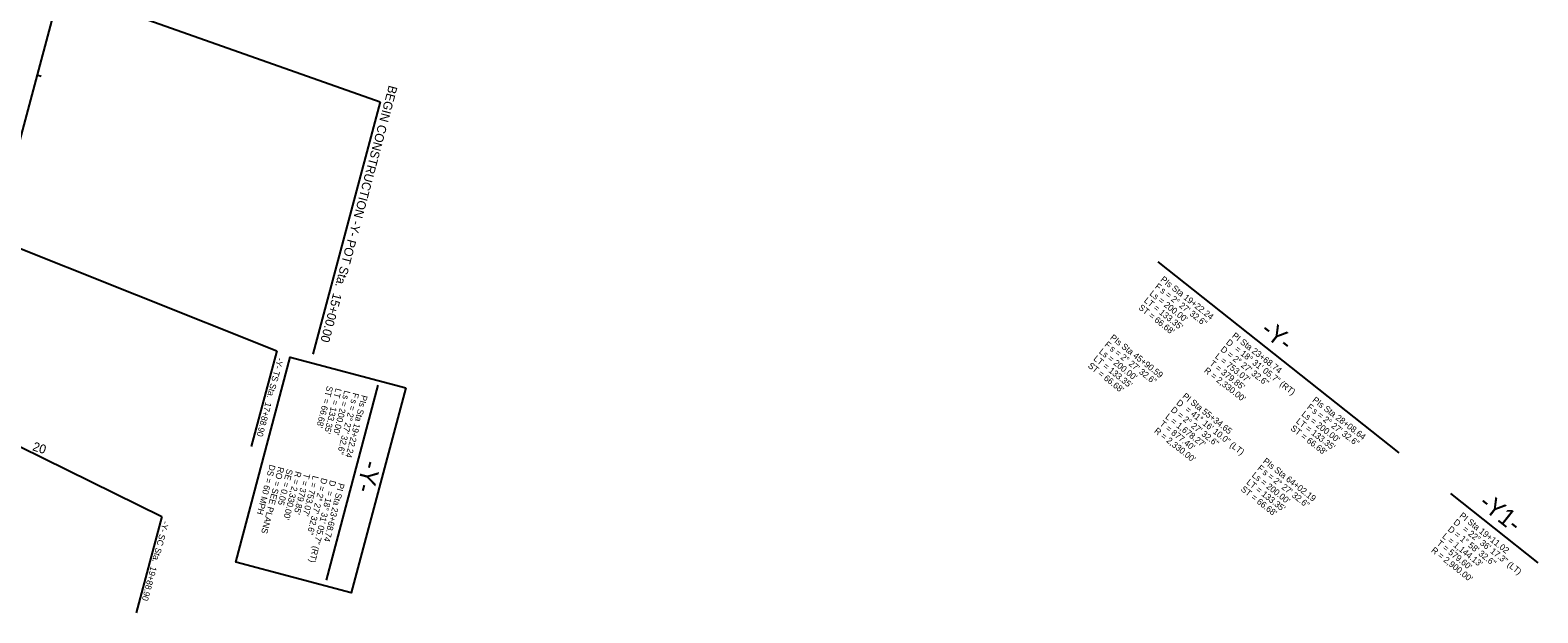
# Model space of a CAD drawing. Extents: x 1778969 to 1790720, y 807089 to 817794.
# Drawn here: x 1783038 to 1784726, y 814841 to 815493 of the extents above; entities that cross this region are included whole.
import ezdxf

# ---------------------------------------------------------------- set-up
doc = ezdxf.new("R2010")
doc.units = 0
for name, color, linetype in [('Prop Horizontal Alignment', 7, 'Continuous'), ('Prop Horizontal Alignment Curve and Spiral Data', 7, 'Continuous'), ('Prop Horizontal Alignment Station Label', 7, 'Continuous'), ('Prop Horizontal Alignment Tick Label', 7, 'Continuous'), ('Prop Horizontal Alignment Tick Small', 7, 'Continuous')]:
    doc.layers.add(name, color=color, linetype=linetype)

msp = doc.modelspace()

# ---------------------------------------------------------------- linework, layer by layer
at = {"layer": 'Prop Horizontal Alignment'}
msp.add_line((1783199.9, 816022.5), (1782996.6, 815260.3), dxfattribs=at)
at = {"layer": 'Prop Horizontal Alignment Station Label'}
for p, q in [((1783071, 815539.4), (1783429.8, 815412.7)), ((1783429.8, 815412.7), (1783354.4, 815130.1)), ((1782998, 815259.7), (1783313.8, 815134)), ((1784300.8, 815233.4), (1784570.8, 815019.7)), ((1783313.8, 815134), (1783285.1, 815026.6)), ((1783427.2, 815095.3), (1783369.3, 814877.3)), ((1782943.7, 815067.2), (1783185.3, 814948.6)), ((1784628.4, 814974.1), (1784726.4, 814896.5)), ((1783185.3, 814948.6), (1783156.5, 814840.6))]:
    msp.add_line(p, q, dxfattribs=at)
msp.add_lwpolyline([(1783458.3, 815092.4), (1783397.3, 814862.9), (1783267.9, 814897.3), (1783328.9, 815126.8)], close=True, dxfattribs=at)
at = {"layer": 'Prop Horizontal Alignment Tick Small'}
msp.add_line((1783045.3, 815442.8), (1783050.1, 815441.5), dxfattribs=at)

# ---------------------------------------------------------------- texts
at = {"layer": 'Prop Horizontal Alignment Curve and Spiral Data'}
for s, rotation, p in [('PIs Sta 19+22.24', 321.8415, (1784303.1, 815212.6)), ("Ls = 200.00'", 321.8415, (1784290.8, 815196.8)), ('F', 321.8415, (1784296.9, 815204.7)), ('s = 2%%d 27\' 32.6"', 321.8415, (1784302.8, 815200)), ("ST = 66.68'", 321.8415, (1784278.4, 815181.1)), ("LT = 133.35'", 321.8415, (1784284.6, 815189)), ('F', 321.7004, (1784240.4, 815139.7)), ('PIs Sta 45+90.59', 321.7004, (1784246.6, 815147.5)), ('D', 321.9988, (1784376.5, 815142.1)), ('PI Sta 23+68.74', 321.9988, (1784383.2, 815149.6)), ("LT = 133.35'", 321.7004, (1784228, 815124)), ("Ls = 200.00'", 321.7004, (1784234.2, 815131.8)), ('s = 2%%d 27\' 32.6"', 321.7004, (1784246.3, 815135)), ("L = 753.07'", 321.9988, (1784364.2, 815126.4)), ('D = 2%%d 27\' 32.6"', 321.9988, (1784370.3, 815134.3)), ('= 18%%d 31\' 05.7" (RT)', 321.9988, (1784386.3, 815134.6)), ("ST = 66.68'", 321.7004, (1784221.8, 815116.1)), ("R = 2,330.00'", 321.9988, (1784351.9, 815110.6)), ("T = 379.85'", 321.9988, (1784358, 815118.5)), ("ST = 66.68'", 255.3267, (1783370.3, 815095.1)), ("LT = 133.35'", 255.3267, (1783380, 815092.5)), ("Ls = 200.00'", 255.3267, (1783389.7, 815090)), ('s = 2%%d 27\' 32.6"', 255.3267, (1783397.5, 815080.2)), ('PIs Sta 19+22.24', 255.3267, (1783409, 815084.9)), ('F', 255.3267, (1783399.4, 815087.5)), ('D', 321.6702, (1784320.8, 815074.5)), ('PI Sta 55+34.65', 321.6702, (1784327.6, 815081.9)), ('PIs Sta 28+08.64', 322.4509, (1784473.2, 815077.6)), ("L = 1,678.27'", 321.6702, (1784308.4, 815058.8)), ('D = 2%%d 27\' 32.6"', 321.6702, (1784314.6, 815066.7)), ('= 41%%d 16\' 10.0" (LT)', 321.6702, (1784330.7, 815066.9)), ("Ls = 200.00'", 322.4509, (1784461, 815061.8)), ('F', 322.4509, (1784467.1, 815069.7)), ('s = 2%%d 27\' 32.6"', 322.4509, (1784473, 815065.1)), ("R = 2,330.00'", 321.6702, (1784296, 815043.1)), ("T = 877.40'", 321.6702, (1784302.2, 815051)), ("ST = 66.68'", 322.4509, (1784448.8, 815045.9)), ("LT = 133.35'", 322.4509, (1784454.9, 815053.8)), ('PIs Sta 64+02.19', 321.8229, (1784417.8, 815009.2)), ('DS = 60 MPH', 255.484, (1783305.9, 815007.1)), ('RO = SEE PLANS', 255.484, (1783315.6, 815004.6)), ('SE = 0.05', 255.484, (1783325.3, 815002.1)), ("R = 2,330.00'", 255.484, (1783335, 814999.6)), ("T = 379.85'", 255.484, (1783344.6, 814997.1)), ("L = 753.07'", 255.484, (1783354.3, 814994.6)), ("Ls = 200.00'", 321.8229, (1784405.4, 814993.5)), ('F', 321.8229, (1784411.6, 815001.3)), ('s = 2%%d 27\' 32.6"', 321.8229, (1784417.5, 814996.7)), ('= 18%%d 31\' 05.7" (RT)', 255.484, (1783370.7, 814977.6)), ('D = 2%%d 27\' 32.6"', 255.484, (1783364, 814992.1)), ('PI Sta 23+68.74', 255.484, (1783383.2, 814986.4)), ('D', 255.484, (1783373.7, 814989.6)), ("ST = 66.68'", 321.8229, (1784393.1, 814977.8)), ("LT = 133.35'", 321.8229, (1784399.3, 814985.6)), ('D', 321.6272, (1784631.2, 814940.8)), ('PI Sta 19+11.02', 321.6272, (1784637.9, 814948.2)), ("L = 1,144.13'", 321.6272, (1784618.7, 814925.1)), ('D = 1%%d 58\' 32.6"', 321.6272, (1784624.9, 814932.9)), ('= 22%%d 36\' 17.3" (LT)', 321.6272, (1784641.4, 814933)), ("R = 2,900.00'", 321.6272, (1784606.3, 814909.4)), ("T = 579.60'", 321.6272, (1784612.5, 814917.3))]:
    msp.add_text(s, height=7, rotation=rotation, dxfattribs=at).set_placement(p)
at = {"layer": 'Prop Horizontal Alignment Station Label'}
for s, height, rotation, p in [('BEGIN CONSTRUCTION -Y- POT Sta.  15+00.00', 10, 255.0043, (1783439.5, 815431.7)), ('-Y-', 20, 321.6309, (1784414.5, 815154.4)), ('-Y- TS Sta.  17+88.90', 7, 255.0043, (1783314.7, 815126.6)), ('-Y-', 20, 255.1161, (1783411.6, 815012.5)), ('-Y1-', 20, 321.6309, (1784658.9, 814960.9)), ('-Y- SC Sta.  19+88.90', 7, 255.0142, (1783186.4, 814943.8))]:
    msp.add_text(s, height=height, rotation=rotation, dxfattribs=at).set_placement(p)
at = {"layer": 'Prop Horizontal Alignment Tick Label'}
msp.add_text('20', height=10, rotation=342.3352, dxfattribs=at).set_placement((1783039.5, 815022.7))

doc.saveas('drawing.dxf')
